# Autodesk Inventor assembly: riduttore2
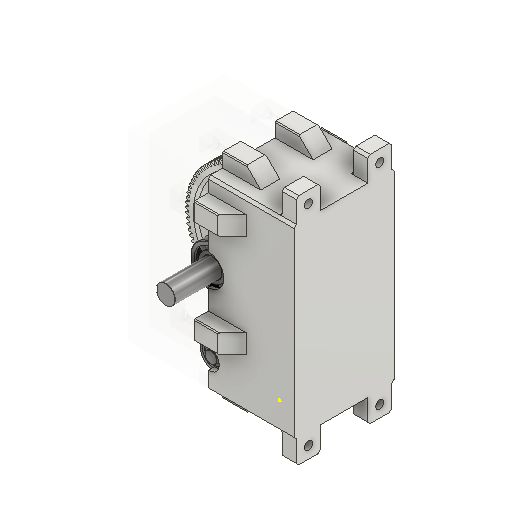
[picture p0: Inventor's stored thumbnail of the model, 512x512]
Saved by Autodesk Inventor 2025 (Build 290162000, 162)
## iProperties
Created: 2026-05
Part Number: riduttore2
Document SubType Name: Assembly
Designer: R5800u
Author: R5800u
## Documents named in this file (15)
- C:\Users\Ryzen5700u\Desktop\riduttore pompa\riduttore2.iam
- C:\Users\Ryzen5700u\Desktop\riduttore pompa\Ingranaggi cilindrici1.iam
- C:\Users\Ryzen5700u\Desktop\riduttore pompa\Albero1.ipt
- C:\Users\Ryzen5700u\Desktop\riduttore pompa\Albero2.ipt
- C:\Users\Ryzen5700u\Desktop\riduttore pompa\Connessione a chiavetta4.iam
- C:\Users\Ryzen5700u\Desktop\riduttore pompa\Connessione a chiavetta5.iam
- C:\Users\Ryzen5700u\Desktop\riduttore pompa\distanziale_condeotta.ipt
- C:\Users\Ryzen5700u\Desktop\riduttore pompa\distanziale_pignone.ipt
- C:\Users\Ryzen5700u\Desktop\riduttore pompa\BS 290 SKF - SKF 6308-Z.ipt
- C:\Users\Ryzen5700u\Desktop\riduttore pompa\BS 290 SKF - SKF 6305-Z.ipt
- C:\Users\Ryzen5700u\Desktop\riduttore pompa\carter.ipt
- C:\Users\Ryzen5700u\Desktop\riduttore pompa\riduttore2\Design Accelerator\Connessione a chiavetta1.iam
- C:\Users\Ryzen5700u\Desktop\riduttore pompa\riduttore2\Design Accelerator\Connessione a chiavetta2.iam
- C:\Users\Ryzen5700u\Desktop\riduttore pompa\riduttore2\Design Accelerator\Connessione a chiavetta3.iam
- C:\Users\Ryzen5700u\Desktop\riduttore pompa\carter_MIR.ipt
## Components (17 placed, 9 different names)
1. Ingranaggi cilindrici:1 [sub-assembly] — Coincidente:1, Coincidente:2, Coincidente:3, Coincidente:4, Coincidente:19, Coincidente:20, Allineato:3
2. Albero:1
3. Albero:1 — Coincidente:3, Coincidente:4, Coincidente:12, Coincidente:14, Coincidente:18
4. BS 290 SKF- con schermatura Z SKF 6308-Z:1 — Coincidente:6
5. BS 290 SKF- con schermatura Z SKF 6305-Z:2 — Coincidente:12
6. Connessione a chiavetta:2 [sub-assembly] — Allineato:1, Angolo:1, Coincidente:13
7. Connessione a chiavetta:4 [sub-assembly]
8. BS 290 SKF- con schermatura Z SKF 6305-Z:1 — Coincidente:14, Allineato:2
9. distanziale_condeotta:1 — Coincidente:15, Coincidente:17, Coincidente:20
10. BS 290 SKF- con schermatura Z SKF 6308-Z:2 — Coincidente:16, Coincidente:17, Allineato:2
11. distanziale_pignone:1 — Coincidente:18, Coincidente:19
12. carter:1
13. Connessione a chiavetta:5 [sub-assembly]
14. Connessione a chiavetta:6 [sub-assembly]
15. Connessione a chiavetta:7 [sub-assembly]
16. Connessione a chiavetta:8 [sub-assembly]
17. carter_MIR:1 — Coincidente:21
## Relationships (19: Mate 15, Flush 3, Angle 1)
- Coincidente:1 [Mate]: Ingranaggi cilindrici:1
- Coincidente:2 [Mate]: Ingranaggi cilindrici:1
- Coincidente:3 [Mate]: Ingranaggi cilindrici:1 ↔ Albero:1
- Coincidente:4 [Mate]: Ingranaggi cilindrici:1 ↔ Albero:1
- Coincidente:6 [Mate]: BS 290 SKF- con schermatura Z SKF 6308-Z:1
- Coincidente:12 [Mate]: Albero:1 ↔ BS 290 SKF- con schermatura Z SKF 6305-Z:2
- Allineato:1 [Flush]: Connessione a chiavetta:2
- Angolo:1 [Angle]: Connessione a chiavetta:2
- Coincidente:13 [Mate]: Connessione a chiavetta:2
- Coincidente:14 [Mate]: Albero:1 ↔ BS 290 SKF- con schermatura Z SKF 6305-Z:1
- Coincidente:15 [Mate]: distanziale_condeotta:1
- Coincidente:16 [Mate]: BS 290 SKF- con schermatura Z SKF 6308-Z:2
- Coincidente:17 [Mate]: distanziale_condeotta:1 ↔ BS 290 SKF- con schermatura Z SKF 6308-Z:2
- Allineato:2 [Flush]: BS 290 SKF- con schermatura Z SKF 6305-Z:1 ↔ BS 290 SKF- con schermatura Z SKF 6308-Z:2
- Coincidente:18 [Mate]: Albero:1 ↔ distanziale_pignone:1
- Coincidente:19 [Mate]: Ingranaggi cilindrici:1 ↔ distanziale_pignone:1
- Coincidente:20 [Mate]: Ingranaggi cilindrici:1 ↔ distanziale_condeotta:1
- Allineato:3 [Flush]: Ingranaggi cilindrici:1
- Coincidente:21 [Mate]: carter_MIR:1
